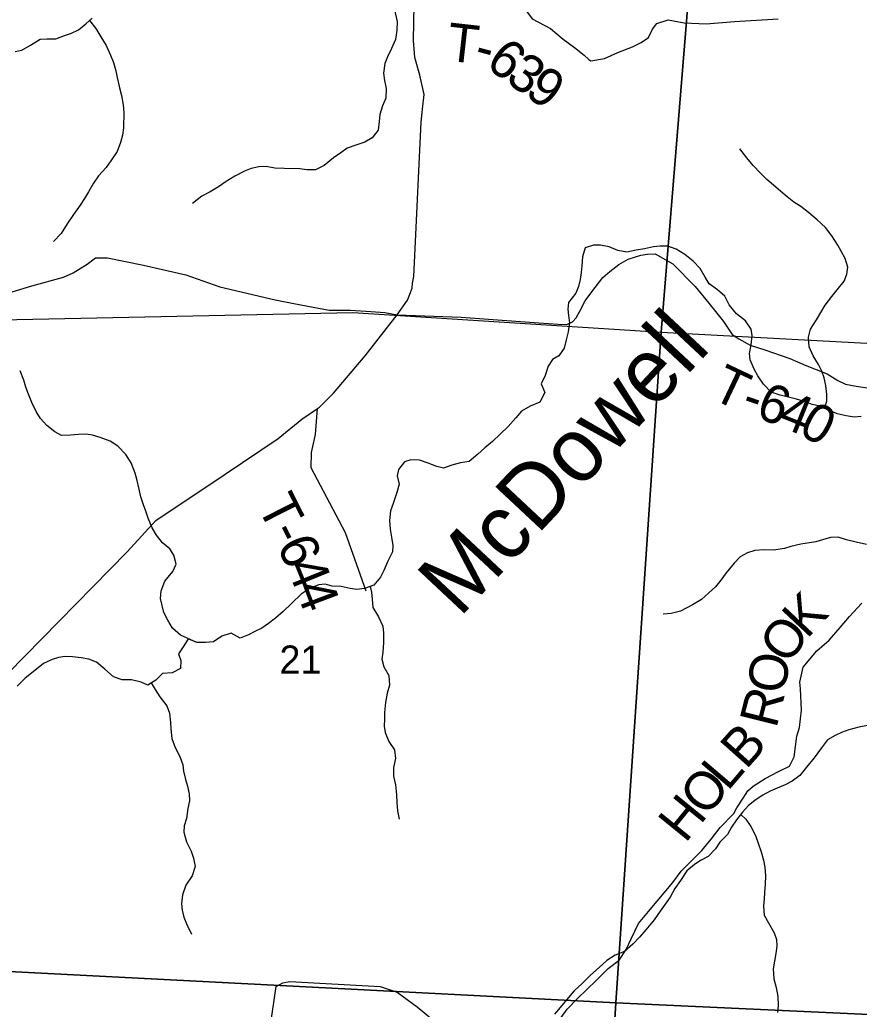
# Model space of a CAD drawing. Extents: x 0 to 40.8, y 0 to 22.
# Drawn here: x 4.714 to 5.961, y 19.177 to 20.647 of the extents above; entities that cross this region are included whole.
import ezdxf

# ---------------------------------------------------------------- set-up
doc = ezdxf.new("R2010")
doc.units = 0
for name, color, linetype in [('GM_X_County_Road', 7, 'Continuous'), ('GM_X_Minor_River', 7, 'Continuous'), ('GM_X_Minor_River_Text', 7, 'Continuous'), ('GM_X_Section', 7, 'Continuous'), ('GM_X_Section_Text', 7, 'Continuous'), ('GM_X_State_Route', 7, 'Continuous'), ('GM_X_Township_Road', 7, 'Continuous'), ('GM_X_Township_Road_Text', 7, 'Continuous')]:
    doc.layers.add(name, color=color, linetype=linetype)

msp = doc.modelspace()

# ---------------------------------------------------------------- linework, layer by layer
at = {"layer": 'GM_X_County_Road'}
for points in [[(5.7251, 20.9), (4.7052, 20.9), (4.6616, 20.2002), (5.209, 20.2119), (5.6669, 20.1827)], [(6.7134, 20.9), (5.7251, 20.9), (5.6669, 20.1827), (6.1945, 20.1544), (6.6517, 20.1638)]]:
    msp.add_lwpolyline(points, close=True, dxfattribs=at)
at = {"layer": 'GM_X_Minor_River'}
for points in [[(5.2686, 20.6697), (5.2745, 20.6439), (5.2741, 20.631), (5.2721, 20.6174), (5.266, 20.6038), (5.2602, 20.5917), (5.2564, 20.5815), (5.2544, 20.5671), (5.2558, 20.5564), (5.2584, 20.5447), (5.2579, 20.5303), (5.2529, 20.5189), (5.2487, 20.5057), (5.2479, 20.4954), (5.2466, 20.4826), (5.2375, 20.4712), (5.2265, 20.4648), (5.2132, 20.4604), (5.2003, 20.4559), (5.1908, 20.4491), (5.1801, 20.4416), (5.1664, 20.4299), (5.1535, 20.4236), (5.1403, 20.4236), (5.1301, 20.4252), (5.1066, 20.4254), (5.093, 20.4262), (5.0801, 20.4286), (5.0691, 20.4279), (5.0578, 20.4257), (5.0479, 20.4219), (5.0335, 20.4144), (5.0205, 20.4062), (5.0095, 20.3986), (4.997, 20.3908), (4.9844, 20.3844), (4.9707, 20.3738)], [(4.7071, 20.5992), (4.7173, 20.6014), (4.7303, 20.6089), (4.7443, 20.6175), (4.7542, 20.6182), (4.7678, 20.6181), (4.7807, 20.623), (4.791, 20.6267), (4.8012, 20.6316), (4.8122, 20.6403), (4.8218, 20.6489)], [(4.8177, 20.6453), (4.827, 20.6337), (4.8348, 20.6212), (4.8427, 20.6082), (4.8491, 20.5938), (4.8535, 20.5831), (4.8569, 20.5706), (4.8587, 20.5607), (4.8624, 20.5455), (4.865, 20.5341), (4.8679, 20.5201), (4.8686, 20.5087), (4.8684, 20.486), (4.8669, 20.4753), (4.8638, 20.4644), (4.8588, 20.4511), (4.8496, 20.4371), (4.8427, 20.4273), (4.8313, 20.4145), (4.8236, 20.4039), (4.8164, 20.3911), (4.8102, 20.3809), (4.8041, 20.3711), (4.7938, 20.3571), (4.7846, 20.3435), (4.7755, 20.3291), (4.7644, 20.3174)], [(5.9095, 20.0696), (5.9128, 20.08), (5.9128, 20.0902), (5.9114, 20.1035), (5.9088, 20.1145), (5.9055, 20.1244), (5.9002, 20.1347), (5.8924, 20.1472), (5.8864, 20.1606), (5.8857, 20.175), (5.8884, 20.1871), (5.8972, 20.2011), (5.9041, 20.2116), (5.9102, 20.2226), (5.9202, 20.2354), (5.9282, 20.2456), (5.9385, 20.2585), (5.9423, 20.2687), (5.9439, 20.2793), (5.9398, 20.2922), (5.9346, 20.3017), (5.9293, 20.312), (5.92, 20.3257), (5.9106, 20.3379), (5.8985, 20.3493), (5.8857, 20.3604), (5.874, 20.3692), (5.8639, 20.3757), (5.8541, 20.3834), (5.8443, 20.3914), (5.8337, 20.4009), (5.8239, 20.4093), (5.8145, 20.4189), (5.8036, 20.4303), (5.7942, 20.4417), (5.7837, 20.4547)], [(5.7988, 20.1414), (5.7981, 20.1508), (5.8005, 20.1637), (5.8017, 20.1774), (5.8006, 20.1869), (5.792, 20.1994), (5.7788, 20.2097), (5.7675, 20.2231), (5.7615, 20.236), (5.7502, 20.2456), (5.7378, 20.2544), (5.7322, 20.2642), (5.7247, 20.2772), (5.7145, 20.2879), (5.7017, 20.2978), (5.6889, 20.3058), (5.6764, 20.3101), (5.6654, 20.3102), (5.6552, 20.3091), (5.642, 20.3065), (5.6298, 20.3043), (5.6158, 20.3013), (5.6022, 20.3037), (5.5897, 20.3091), (5.5765, 20.3118), (5.5663, 20.3119), (5.5541, 20.3078), (5.5499, 20.2945), (5.549, 20.2809), (5.5478, 20.271), (5.5463, 20.2608), (5.5439, 20.2506), (5.5401, 20.2407), (5.529, 20.2264), (5.5282, 20.2169), (5.5293, 20.2071), (5.5307, 20.1964), (5.5287, 20.1828), (5.5256, 20.1711), (5.5225, 20.1589), (5.5149, 20.1476), (5.5054, 20.142), (5.4989, 20.1318), (5.4946, 20.1181), (5.4885, 20.1057), (5.4941, 20.0931), (5.4864, 20.0788), (5.4724, 20.0728), (5.4591, 20.0653), (5.4511, 20.0551), (5.4396, 20.0422), (5.4278, 20.0309), (5.416, 20.02), (5.405, 20.0106), (5.3943, 20.0012), (5.3818, 19.9906), (5.3689, 19.9884), (5.3556, 19.9851), (5.3435, 19.9806), (5.3336, 19.983), (5.3208, 19.988), (5.3076, 19.9922), (5.2951, 19.9931), (5.2856, 19.9901), (5.2765, 19.9788), (5.2749, 19.9693), (5.2775, 19.9568), (5.2743, 19.9443), (5.2689, 19.928), (5.2647, 19.917), (5.2635, 19.903), (5.2645, 19.8897), (5.266, 19.8783), (5.2682, 19.8658), (5.2677, 19.8563), (5.2608, 19.8423), (5.2547, 19.8287), (5.2501, 19.8189), (5.2398, 19.8068), (5.2261, 19.802), (5.2148, 19.8001), (5.2049, 19.8017), (5.1913, 19.8048), (5.1781, 19.8053), (5.1679, 19.8084), (5.1584, 19.8073), (5.1455, 19.8021), (5.1322, 19.7934), (5.1181, 19.7802), (5.1055, 19.7678), (5.0941, 19.758), (5.0835, 19.7497), (5.0739, 19.7429), (5.0633, 19.7381), (5.0538, 19.7328), (5.0417, 19.7283), (5.0281, 19.7353), (5.0144, 19.7312), (5.0019, 19.7225), (4.9901, 19.7218), (4.9769, 19.7215)], [(5.9637, 20.0573), (5.9535, 20.0562), (5.9414, 20.0582), (5.9282, 20.0613), (5.9161, 20.0667), (5.9029, 20.0725), (5.8911, 20.0752), (5.881, 20.0791), (5.8677, 20.0829), (5.8579, 20.0856), (5.8435, 20.0888), (5.8299, 20.0934), (5.8186, 20.1052), (5.8104, 20.1178), (5.8048, 20.1277), (5.7988, 20.1414)], [(4.9769, 19.7215), (4.9531, 19.7327), (4.9411, 19.743), (4.9343, 19.7548), (4.9283, 19.7662), (4.9254, 19.7764), (4.9232, 19.7871), (4.9244, 19.7984), (4.9298, 19.8128), (4.9416, 19.8272), (4.9466, 19.8381), (4.9429, 19.8511), (4.9369, 19.8606), (4.9263, 19.8697), (4.9173, 19.8812), (4.9109, 19.8918), (4.905, 19.9063), (4.9012, 19.9165), (4.8979, 19.926), (4.8942, 19.9378), (4.8912, 19.9515), (4.8887, 19.9621), (4.8857, 19.9731), (4.8794, 19.9887), (4.8715, 20.0009), (4.8598, 20.0131), (4.8485, 20.0208), (4.8338, 20.0262), (4.8224, 20.0296), (4.8126, 20.0312), (4.8012, 20.0305), (4.7895, 20.0295), (4.7759, 20.0292), (4.7661, 20.0345), (4.7544, 20.0441), (4.745, 20.0544), (4.7386, 20.0646), (4.7319, 20.0783), (4.727, 20.0905), (4.7233, 20.1008), (4.72, 20.1114), (4.7148, 20.1251)], [(5.9716, 19.8673), (5.9565, 19.8704), (5.9421, 19.8743), (5.9297, 19.8782), (5.9183, 19.8775), (5.9062, 19.8741), (5.8963, 19.8711), (5.8868, 19.8697), (5.874, 19.8679), (5.8595, 19.8642), (5.8501, 19.8612), (5.8334, 19.8586), (5.819, 19.8591), (5.8057, 19.8584), (5.7951, 19.8547), (5.7841, 19.8491), (5.775, 19.8393), (5.7631, 19.8253), (5.7555, 19.814), (5.7475, 19.8041), (5.7376, 19.7955), (5.7265, 19.7853), (5.7132, 19.7774), (5.6954, 19.7681), (5.6817, 19.7647), (5.6696, 19.7637)], [(5.2346, 19.805), (5.2363, 19.7962), (5.2374, 19.786), (5.2385, 19.7738), (5.2467, 19.7597), (5.2534, 19.746), (5.2545, 19.7354), (5.2544, 19.7214), (5.2532, 19.7074), (5.252, 19.6968), (5.2549, 19.6857), (5.2624, 19.6728), (5.2631, 19.658), (5.26, 19.6463), (5.2573, 19.6323), (5.256, 19.6178), (5.256, 19.6076), (5.2555, 19.5974), (5.2566, 19.5879), (5.2622, 19.5746), (5.2705, 19.5624), (5.2723, 19.5491), (5.2692, 19.5359), (5.2691, 19.5233), (5.2724, 19.5104), (5.2738, 19.4956), (5.2741, 19.4839), (5.2752, 19.4717), (5.2774, 19.4592)], [(4.9769, 19.7215), (4.9644, 19.7273), (4.9576, 19.7167), (4.9499, 19.705), (4.9536, 19.6951), (4.9528, 19.683), (4.9406, 19.6766), (4.9262, 19.6756), (4.9163, 19.6658), (4.9042, 19.6583), (4.8944, 19.6625), (4.88, 19.6664), (4.8664, 19.6661), (4.8535, 19.6707), (4.8407, 19.6818), (4.8279, 19.6925), (4.8166, 19.6971), (4.8052, 19.699), (4.7924, 19.7003), (4.7818, 19.7007), (4.7715, 19.6992), (4.7621, 19.6963), (4.7495, 19.6903), (4.7339, 19.6782), (4.7221, 19.6688), (4.7103, 19.6568)], [(4.9094, 19.6615), (4.9151, 19.6517), (4.9222, 19.6407), (4.9328, 19.6274), (4.9365, 19.6167), (4.9379, 19.6027), (4.9386, 19.5932), (4.94, 19.5792), (4.9449, 19.5659), (4.952, 19.5525), (4.9561, 19.54), (4.9571, 19.5305), (4.9605, 19.518), (4.9631, 19.5081), (4.9656, 19.4967), (4.966, 19.4865), (4.964, 19.4751), (4.9616, 19.4603), (4.9585, 19.4494), (4.9577, 19.4399), (4.9618, 19.4254), (4.9689, 19.4117), (4.9722, 19.4015), (4.9748, 19.389), (4.9702, 19.375), (4.961, 19.361), (4.956, 19.347), (4.9544, 19.3337), (4.9555, 19.3242), (4.9577, 19.3136), (4.9622, 19.3026), (4.9693, 19.2885)], [(5.973, 19.5984), (5.9605, 19.5958), (5.9453, 19.5917), (5.9347, 19.588), (5.9252, 19.5835), (5.9138, 19.5771), (5.905, 19.5651), (5.8939, 19.5503), (5.8825, 19.5367), (5.8726, 19.5243), (5.8612, 19.5156), (5.8509, 19.5104), (5.8388, 19.5052), (5.8285, 19.5007), (5.8175, 19.495), (5.8061, 19.4875), (5.7958, 19.4792), (5.7874, 19.4694), (5.7786, 19.4581), (5.7714, 19.4475), (5.7653, 19.4366), (5.7538, 19.4253), (5.7473, 19.4154), (5.7367, 19.4037), (5.726, 19.3981), (5.7161, 19.3917), (5.7051, 19.3823), (5.6955, 19.368), (5.6871, 19.3563), (5.6799, 19.3434), (5.6726, 19.3332), (5.6654, 19.3226), (5.6562, 19.3098), (5.644, 19.2947), (5.6348, 19.2838), (5.6249, 19.2736), (5.6124, 19.2627), (5.5983, 19.2574), (5.5862, 19.2492), (5.5747, 19.239), (5.5618, 19.2273), (5.5496, 19.2153), (5.5374, 19.2043), (5.526, 19.1907), (5.5168, 19.1794), (5.5084, 19.1696)], [(5.7849, 19.4662), (5.7927, 19.4592), (5.7998, 19.4485), (5.8069, 19.4348), (5.811, 19.4238), (5.8151, 19.4109), (5.8188, 19.3983), (5.8206, 19.3877), (5.8217, 19.3752), (5.8212, 19.3627), (5.8204, 19.3502), (5.8199, 19.3407), (5.8187, 19.3301), (5.8198, 19.3164), (5.8262, 19.3054), (5.8348, 19.2905), (5.8381, 19.2803), (5.8384, 19.2704), (5.8369, 19.2598), (5.8329, 19.2371), (5.8343, 19.2223), (5.8377, 19.2094), (5.8399, 19.1957), (5.8405, 19.1824), (5.8393, 19.1722)]]:
    msp.add_lwpolyline(points, dxfattribs=at)
at = {"layer": 'GM_X_Section'}
for points in [[(4.6616, 20.2002), (5.209, 20.2119), (5.6669, 20.1827), (5.5995, 19.1863), (4.6019, 19.2378)], [(5.6669, 20.1827), (6.1945, 20.1544), (6.6517, 20.1638), (6.5668, 19.1421), (5.5995, 19.1863)]]:
    msp.add_lwpolyline(points, close=True, dxfattribs=at)
for points in [[(5.1222, 18.2458), (4.9546, 18.2574), (4.4961, 18.3336), (4.6019, 19.2378), (5.5995, 19.1863), (5.5864, 18.978)], [(5.5863, 18.9775), (5.5995, 19.1863), (6.5668, 19.1421), (6.5505, 18.9672)]]:
    msp.add_lwpolyline(points, dxfattribs=at)
at = {"layer": 'GM_X_State_Route'}
msp.add_lwpolyline([(4.5949, 19.5728), (4.8739, 19.8562), (4.9164, 19.9026), (5.0191, 19.9714), (5.0981, 20.0244), (5.1329, 20.0534), (5.1565, 20.0692), (5.1593, 20.0711), (5.1799, 20.0918), (5.2271, 20.1474), (5.2746, 20.2082), (5.29, 20.2301), (5.2968, 20.248), (5.2975, 20.2551), (5.2996, 20.2653), (5.3102, 20.4946), (5.3124, 20.514), (5.3146, 20.5356), (5.3085, 20.5645), (5.3009, 20.5905), (5.299, 20.6159), (5.2997, 20.6699)], dxfattribs=at)
at = {"layer": 'GM_X_Township_Road'}
for points in [[(5.3001, 20.6888), (5.4562, 20.6732), (5.4752, 20.6477), (5.5022, 20.6335), (5.5212, 20.6179), (5.5379, 20.6053), (5.5523, 20.5942), (5.5592, 20.5873), (5.5622, 20.5854), (5.5824, 20.5892), (5.6022, 20.5979), (5.6243, 20.6062), (5.6372, 20.613), (5.6479, 20.6202), (5.654, 20.6327), (5.6601, 20.6411), (5.6769, 20.6463), (5.7008, 20.6421), (5.7336, 20.6405), (5.7758, 20.6438), (5.8325, 20.6474), (5.8405, 20.6478)], [(5.2354, 20.2133), (5.2564, 20.212), (5.2746, 20.2082), (5.3698, 20.2048), (5.4851, 20.1965), (5.514, 20.1942), (5.5266, 20.1941), (5.535, 20.1979), (5.5407, 20.204), (5.5457, 20.2135), (5.5541, 20.229), (5.564, 20.2423), (5.58, 20.2636), (5.5903, 20.2727), (5.604, 20.2829), (5.6177, 20.2909), (5.6367, 20.2969), (5.6466, 20.2984), (5.6577, 20.2987), (5.6839, 20.2838), (5.717, 20.2502), (5.7375, 20.2255), (5.7591, 20.1984), (5.7724, 20.1793), (5.7823, 20.1725), (5.799, 20.1633), (5.8207, 20.1564), (5.8576, 20.1433), (5.8808, 20.1334), (5.9132, 20.1207), (5.9291, 20.1108), (5.9405, 20.1051), (5.9561, 20.1023), (5.9797, 20.0989)], [(4.6715, 20.2331), (4.732, 20.2516), (4.7789, 20.2644), (4.7933, 20.2708), (4.8143, 20.2837), (4.8265, 20.2928), (4.8444, 20.2931), (4.898, 20.2819), (4.9608, 20.2677), (5.0114, 20.25), (5.0936, 20.2304), (5.1213, 20.225), (5.1499, 20.2199), (5.1738, 20.2153), (5.2054, 20.2152), (5.2354, 20.2133)], [(5.2286, 19.7979), (5.1977, 19.8843), (5.1471, 19.9812), (5.1475, 20.0038), (5.1532, 20.0306), (5.1565, 20.0692)], [(5.5006, 19.1398), (5.5269, 19.177), (5.5422, 19.1922), (5.5708, 19.2202), (5.5879, 19.2373), (5.6043, 19.2498), (5.615, 19.2654), (5.6222, 19.2813), (5.6333, 19.3041), (5.6478, 19.3223), (5.684, 19.3652), (5.6962, 19.3819), (5.7111, 19.3967), (5.7271, 19.4126), (5.7408, 19.4297), (5.7542, 19.4468), (5.7748, 19.4677), (5.779, 19.476), (5.7885, 19.4904), (5.7954, 19.5014), (5.8034, 19.5083), (5.8213, 19.5196), (5.8411, 19.5298), (5.8575, 19.5378), (5.8643, 19.5518), (5.8682, 19.5826), (5.872, 19.5952), (5.8751, 19.621), (5.8736, 19.6526), (5.8729, 19.6629), (5.8778, 19.6849), (5.8977, 19.7092), (5.916, 19.7251), (5.9324, 19.7437), (5.9465, 19.76), (5.9648, 19.7798)], [(5.0794, 19.1055), (5.0948, 19.2109), (5.1047, 19.2162), (5.1153, 19.2182), (5.2496, 19.2109), (5.2747, 19.2023), (5.3045, 19.1805), (5.3303, 19.1593)]]:
    msp.add_lwpolyline(points, dxfattribs=at)

# ---------------------------------------------------------------- texts
at = {"layer": 'GM_X_Minor_River_Text'}
msp.add_text('McDowell', height=0.0947, rotation=46.8938, dxfattribs=at).set_placement((5.3673, 19.7573))
at = {"layer": 'GM_X_Section_Text'}
msp.add_text('21', height=0.04186, rotation=0, dxfattribs=at).set_placement((5.0999, 19.6753))
at = {"layer": 'GM_X_Township_Road_Text'}
for s, rotation, p in [('T', 353.5448, (5.3466, 20.5861)), ('-', 345.2179, (5.3867, 20.5817)), ('6', 322.6139, (5.404, 20.5784)), ('3', 324.5225, (5.4335, 20.5559)), ('9', 324.7342, (5.4622, 20.5354)), ('T', 334.6885, (5.7388, 20.0852)), ('6', 338.9079, (5.805, 20.057)), ('-', 340.9374, (5.7834, 20.0645)), ('4', 337.9309, (5.8374, 20.0445)), ('0', 331.8568, (5.8684, 20.032)), ('T', 296.8966, (5.0662, 19.9244)), ('-', 296.0205, (5.0853, 19.8867)), ('6', 294.1812, (5.0954, 19.8661)), ('4', 292.0875, (5.1095, 19.8347)), ('4', 290.6224, (5.1225, 19.8026)), ('K', 46.7622, (5.883, 19.7259)), ('O', 54.0926, (5.8549, 19.6869)), ('O', 81.5544, (5.8502, 19.644)), ('R', 75.9196, (5.8377, 19.5928)), ('B', 48.3412, (5.7928, 19.5318)), ('L', 49.5837, (5.7655, 19.4997)), ('O', 50.7644, (5.7341, 19.4612)), ('H', 50.909, (5.7026, 19.4224))]:
    msp.add_text(s, height=0.0568, rotation=rotation, dxfattribs=at).set_placement(p)

doc.saveas('drawing.dxf')
